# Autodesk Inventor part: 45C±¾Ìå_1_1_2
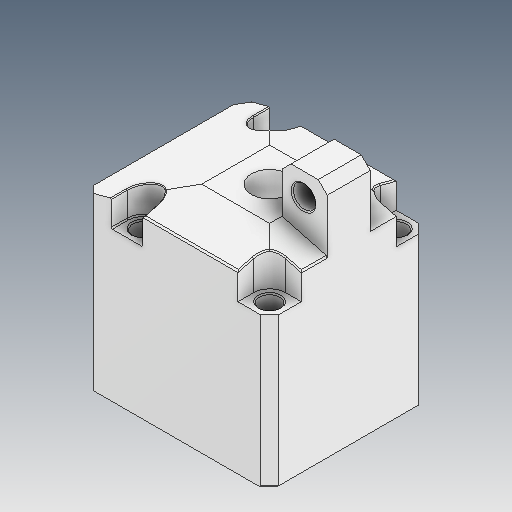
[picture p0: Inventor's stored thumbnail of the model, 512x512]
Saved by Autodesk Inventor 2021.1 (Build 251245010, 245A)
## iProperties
Created: 2021-05
Part Number: 45C±¾Ìå_1_1_2
Material: Ogólny
Document SubType Name: Modeling
Designer: user
Density: 1 g/cm^3
Appearance: Domyślna
Author: user
Revision Number: ÈÎºÎ
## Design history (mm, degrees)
feature "ÇÐ³ý-À­Éì1"
node "Bryła1"
